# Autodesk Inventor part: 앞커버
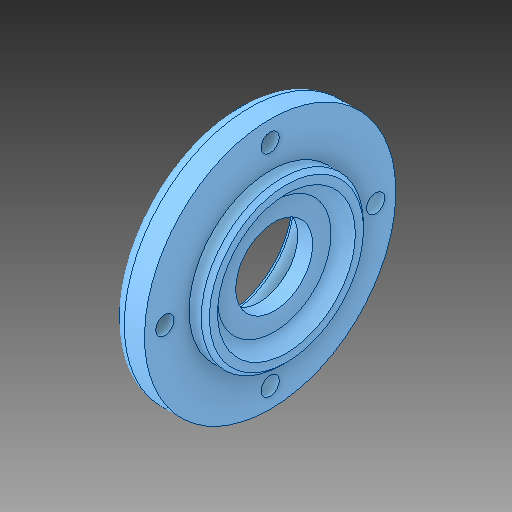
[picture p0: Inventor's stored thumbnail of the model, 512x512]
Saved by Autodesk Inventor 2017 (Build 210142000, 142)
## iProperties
Created: 2024-09
Part Number: 앞커버
Material: 일반
Document SubType Name: Modeling
Designer: MRC
Density: 1 g/cm^3
Appearance: 기본값
Author: jhkim
Sending System: Autodesk Inventor 2025
Preprocessor: ST-DEVELOPER v20
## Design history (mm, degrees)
feature "솔리드1"
node "솔리드2"
